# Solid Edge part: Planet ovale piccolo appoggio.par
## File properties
Title: Planet ovale piccolo appoggio
Author: DESYS
Template: Iso Part.par
Last saved by: s.pallini
Revision: 10
Application: Solid Edge
Tipo di contenuto documento: 0
Accuracy: 0,990
Document Number: 8112
Revision: 0
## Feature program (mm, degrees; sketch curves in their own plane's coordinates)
lofted protrusion "unnamed LoftedProtrusion 1"
lofted cutout "unnamed LoftedCutout 1"
sketch for "unnamed Protrusion 1" plane through (0, 160, 0) normal (0, 1, 0) x-axis (1, 0, 0)
  arc centre (0, 0) radius 160 from (160, 0) to (160, 0) cw
extrude "unnamed Protrusion 1" add finite 7 along +normal
sketch for "ScavoEstrusione_1" #1 plane through (0, 167, 0) normal (0, 1, 0) x-axis (1, 0, 0)
  arc centre (0, 0) radius 120 from (120, 0) to (120, 0)
sketch for "ScavoEstrusione_1" #2 plane through (0, 167, 0) normal (0, 1, 0) x-axis (1, 0, 0)
  circle centre (0, 0) radius 35
extrude "ScavoEstrusione_1" cut finite 50 along -normal
sketch for "Foro_1" plane through (0, 167, 0) normal (0, 1, 0) x-axis (1, 0, 0)
  hole centre (0, 0) bore radius 25
hole "Foro_1" diameter 50 through
fillet "Rotondo_1" radius 10
fillet "Rotondo_2" radius 15
fillet "Rotondo_3" radius 10
fillet "Rotondo_4" radius 5
fillet "Rotondo_5" radius 15
fillet "Rotondo_6" radius 10
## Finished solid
Body 1: solid body, 19 faces, 20 edges, 2 vertices.
  Faces by surface: blend 7, plane 5, cylinder 2, spline 2, torus 2, swept 1
  Edges by curve: intersection 14, circle 6
Bounding box of the edges (mm; curved faces can reach further): 479.445 x 167.000 x 381.318, from (-239.7227, 0, -190.6593) to (239.7227, 167, 190.6593).
Cylindrical faces by radius (mm): R25 x1, R35 x1
Toroidal faces (ring radius, tube radius in mm): R30 r5 x1, R45 r10 x1
Planar faces by outward normal: +y 4, -y 1
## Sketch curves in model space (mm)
arc centre (0, -49.8604, -18.5294) radius 150 from (0, 100, -25) through (0, 70.6732, -107.8135) to (0, 0, -160)
arc centre (0, -49.8604, 18.5294) radius 150 from (0, 100, 25) through (0, 70.6732, 107.8135) to (0, 0, 160)
arc centre (36.6009, -99.6633, 0) radius 200 from (25, 100, 0) through (131.7043, 76.278, 0) to (210, 0, 0)
arc centre (-36.6009, -99.6633, 0) radius 200 from (-25, 100, 0) through (-131.7043, 76.278, 0) to (-210, 0, 0)
circle centre (0, 100, 0) radius 25
ellipse centre (0, 0, 0) radii 210, 160
arc centre (0, 15.7496, -30.777) radius 160 from (0, 0, -190) through (0, 98.2149, -167.8882) to (0, 160, -100)
arc centre (0, 15.7496, 30.777) radius 160 from (0, 0, 190) through (0, 98.2149, 167.8882) to (0, 160, 100)
arc centre (40, 0, 0) radius 200 from (160, 160, 0) through (218.8854, 89.4427, 0) to (240, 0, 0)
arc centre (-40, 0, 0) radius 200 from (-160, 160, 0) through (-218.8854, 89.4427, 0) to (-240, 0, 0)
ellipse centre (0, 160, 0) radii 160, 100
ellipse centre (0, 0, 0) radii 240, 190
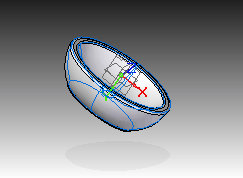
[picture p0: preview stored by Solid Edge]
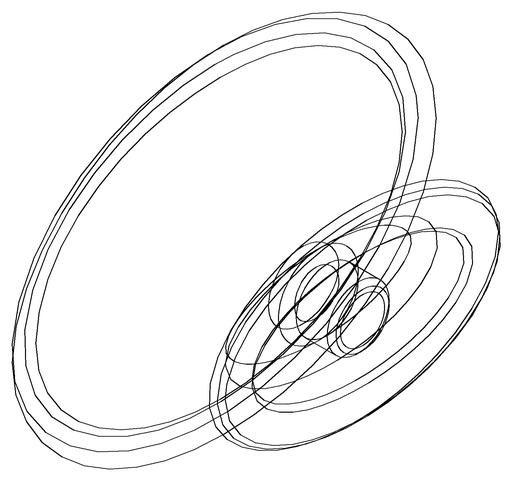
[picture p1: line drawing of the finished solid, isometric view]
